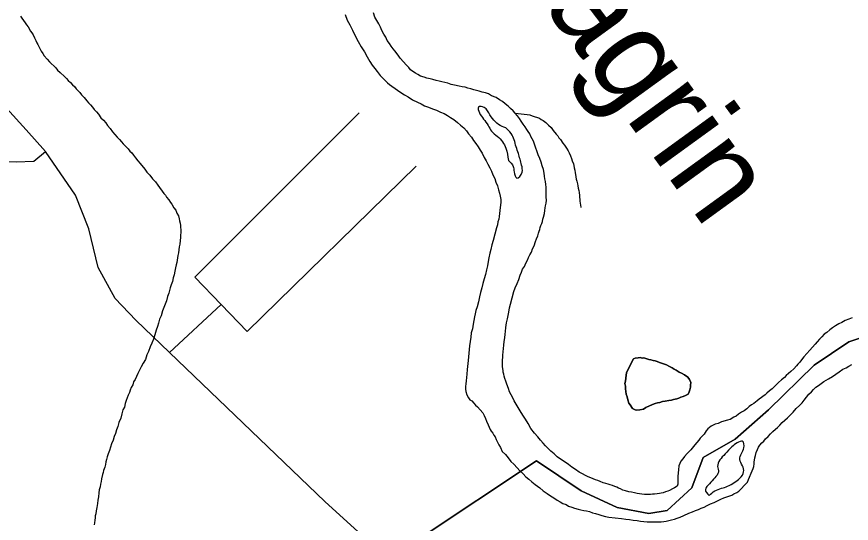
# Model space of a CAD drawing. Extents: x 0 to 34, y 0 to 22.
# Drawn here: x 4.982 to 5.822, y 15.578 to 16.088 of the extents above; entities that cross this region are included whole.
import ezdxf

# ---------------------------------------------------------------- set-up
doc = ezdxf.new("R2010")
doc.units = 0
for name, color, linetype in [('GM_X_City_Street', 7, 'Continuous'), ('GM_X_Corporation', 7, 'Continuous'), ('GM_X_County_Road', 7, 'Continuous'), ('GM_X_Major_River', 7, 'Continuous'), ('GM_X_Major_River_Text', 7, 'Continuous'), ('GM_X_Minor_Lake', 7, 'Continuous'), ('GM_X_Minor_River', 7, 'Continuous')]:
    doc.layers.add(name, color=color, linetype=linetype)

msp = doc.modelspace()

# ---------------------------------------------------------------- linework, layer by layer
at = {"layer": 'GM_X_City_Street'}
msp.add_line((5.13601, 15.74945), (5.1878, 15.79771), dxfattribs=at)
for points in [[(5.1878, 15.79771), (5.16154, 15.82528), (5.32668, 15.99079)], [(3.66207, 15.95316), (3.66945, 15.95309), (3.70802, 15.95138), (3.82256, 15.94662), (3.93928, 15.94584), (3.95443, 15.94583), (3.95914, 15.94579), (3.99989, 15.94543), (4.00319, 15.94546), (4.06636, 15.94982), (4.09371, 15.94871), (4.14798, 15.94309), (4.21615, 15.94459), (4.32069, 15.9434), (4.37523, 15.94224), (4.43166, 15.94259), (4.47924, 15.94418), (4.48737, 15.94445), (4.55589, 15.94253), (4.74017, 15.94206), (4.98153, 15.94149), (4.99934, 15.94206), (5.01105, 15.95188)], [(5.1878, 15.79771), (5.21425, 15.7707), (5.38423, 15.93717)]]:
    msp.add_lwpolyline(points, dxfattribs=at)
at = {"layer": 'GM_X_Corporation'}
for points in [[(5.89854, 16.29354), (5.8973, 15.80142), (5.87587, 15.79084), (5.84552, 15.76912), (5.81951, 15.76039), (5.78464, 15.7367), (5.73873, 15.69197), (5.70509, 15.66223), (5.67317, 15.64391), (5.66151, 15.61336), (5.63685, 15.59059), (5.61834, 15.58765), (5.58642, 15.59364), (5.55018, 15.61018), (5.50536, 15.64041), (5.38614, 15.56141), (5.45057, 15.53342), (5.44414, 15.50982), (5.51454, 15.4828), (5.51493, 15.21351), (4.90537, 15.21691)], [(4.90537, 15.21691), (5.51493, 15.21351), (5.51454, 15.4828), (5.44414, 15.50982), (5.45057, 15.53342), (5.38614, 15.56141), (5.50536, 15.64041), (5.55018, 15.61018), (5.58642, 15.59364), (5.61834, 15.58765), (5.63685, 15.59059), (5.66151, 15.61336), (5.67317, 15.64391), (5.70509, 15.66223), (5.73873, 15.69197), (5.78464, 15.7367), (5.81951, 15.76039), (5.84552, 15.76912), (5.87587, 15.79084), (5.8973, 15.80142), (5.89854, 16.29354)]]:
    msp.add_lwpolyline(points, dxfattribs=at)
at = {"layer": 'GM_X_County_Road'}
msp.add_lwpolyline([(5.44435, 15.50926), (5.36226, 15.54077), (5.34427, 15.55213), (5.29222, 15.59945), (5.13601, 15.74945), (5.10198, 15.78212), (5.08116, 15.80388), (5.06412, 15.83512), (5.05466, 15.87392), (5.04141, 15.90799), (5.01105, 15.95188), (4.99187, 15.97367), (4.81028, 16.17365), (4.78385, 16.20009), (4.7637, 16.23877)], dxfattribs=at)
at = {"layer": 'GM_X_Major_River'}
for points in [[(5.31269, 16.08985), (5.31465, 16.08416), (5.31736, 16.07924), (5.32008, 16.07394), (5.3228, 16.06827), (5.3259, 16.06259), (5.329, 16.0573), (5.3321, 16.052), (5.33481, 16.04708), (5.33752, 16.04254), (5.33984, 16.03876), (5.34253, 16.03537), (5.34484, 16.03234), (5.34792, 16.02819), (5.35061, 16.02555), (5.35291, 16.0233), (5.35522, 16.02103), (5.35752, 16.01916), (5.36555, 16.01353), (5.36861, 16.01128), (5.37243, 16.00903), (5.37625, 16.00679), (5.38046, 16.00378), (5.38542, 16.00155), (5.38924, 15.99969), (5.39268, 15.99782), (5.39649, 15.99634), (5.40068, 15.99486), (5.40449, 15.99337), (5.40869, 15.99151), (5.4125, 15.99003), (5.41556, 15.98816), (5.41862, 15.9859), (5.42206, 15.98404), (5.42589, 15.98103), (5.42895, 15.9784), (5.43202, 15.97577), (5.43471, 15.97275), (5.43702, 15.96973), (5.43972, 15.96633), (5.44203, 15.96293), (5.44434, 15.95991), (5.44666, 15.95651), (5.4486, 15.95311), (5.45053, 15.95008), (5.45247, 15.94592), (5.45479, 15.94252), (5.45635, 15.93911), (5.45828, 15.93532), (5.45984, 15.93191), (5.4614, 15.92851), (5.46334, 15.92472), (5.46452, 15.92093), (5.46608, 15.91714), (5.46688, 15.91335), (5.46806, 15.90993)], [(5.50133, 15.85397), (5.50282, 15.85702), (5.50429, 15.86122), (5.5054, 15.8639), (5.5065, 15.86695), (5.50723, 15.86962), (5.50797, 15.87153), (5.50871, 15.87344), (5.50906, 15.87534), (5.5098, 15.87725), (5.51053, 15.87954), (5.51127, 15.88145), (5.51163, 15.88374), (5.51236, 15.88565), (5.51346, 15.88946), (5.5138, 15.89251), (5.51415, 15.89517), (5.51451, 15.89708), (5.51486, 15.89975), (5.51521, 15.90279), (5.51517, 15.90583), (5.51514, 15.90888), (5.51509, 15.91306), (5.51506, 15.9161), (5.51465, 15.91876), (5.51423, 15.9218), (5.51382, 15.92446), (5.51341, 15.92712), (5.513, 15.93016), (5.5122, 15.93357), (5.51102, 15.93736), (5.50984, 15.94116), (5.50866, 15.94495), (5.5071, 15.94836), (5.50318, 15.95935), (5.50239, 15.96238), (5.50084, 15.96465), (5.49968, 15.96692), (5.49851, 15.96957), (5.49697, 15.97184), (5.49542, 15.97411), (5.49388, 15.97675), (5.49195, 15.9794), (5.49002, 15.98242), (5.48809, 15.98507), (5.48616, 15.98771), (5.48385, 15.99035), (5.48193, 15.99261), (5.47924, 15.99525), (5.47694, 15.99751), (5.47388, 15.99976), (5.4712, 16.00202), (5.46814, 16.00389), (5.4647, 16.00614), (5.46012, 16.00799), (5.45706, 16.00987), (5.45402, 16.01098), (5.45059, 16.0117), (5.44755, 16.01243), (5.44488, 16.01317), (5.44222, 16.0139), (5.43917, 16.01501), (5.43612, 16.01574), (5.43346, 16.01648), (5.43042, 16.01683), (5.42737, 16.01756), (5.42281, 16.01866), (5.41938, 16.01938), (5.41595, 16.02049), (5.41291, 16.02122), (5.40986, 16.02195), (5.4072, 16.02269), (5.40415, 16.02342), (5.40111, 16.02415), (5.39844, 16.02488), (5.39502, 16.02561), (5.39235, 16.02673), (5.38854, 16.02783), (5.38587, 16.02932), (5.38357, 16.03082), (5.3809, 16.03232), (5.3786, 16.0342), (5.37668, 16.03646), (5.37437, 16.03872), (5.36822, 16.04589), (5.36668, 16.04777), (5.36514, 16.05004), (5.36283, 16.05306), (5.3609, 16.05533), (5.35898, 16.05797), (5.35743, 16.06062), (5.35512, 16.06364), (5.35356, 16.06705), (5.35163, 16.07007), (5.34969, 16.07347), (5.34814, 16.07688), (5.34658, 16.08029), (5.34464, 16.0837), (5.34271, 16.0871), (5.34114, 16.09127)], [(5.46806, 15.90993), (5.46885, 15.9069), (5.46927, 15.90348), (5.4693, 15.90082), (5.46896, 15.89777), (5.4686, 15.89548), (5.46826, 15.89244), (5.46791, 15.88939), (5.46757, 15.88635), (5.46722, 15.88368), (5.46649, 15.88101), (5.46614, 15.87797), (5.46504, 15.87491), (5.46176, 15.86233), (5.4603, 15.85775), (5.45921, 15.85317), (5.45849, 15.84936), (5.45741, 15.84479), (5.45669, 15.84098), (5.45598, 15.83678), (5.45489, 15.83259), (5.4538, 15.82801), (5.45271, 15.82382), (5.45125, 15.81886), (5.45016, 15.81467), (5.44907, 15.81009), (5.44798, 15.80552), (5.4469, 15.80056), (5.44544, 15.7956), (5.44434, 15.79179), (5.44362, 15.78836), (5.44289, 15.7853), (5.44217, 15.78187), (5.44146, 15.77806), (5.44075, 15.77349), (5.43966, 15.7693), (5.43933, 15.76511), (5.43862, 15.76054), (5.43791, 15.75635), (5.43757, 15.75254), (5.43723, 15.74873), (5.43689, 15.74531), (5.43656, 15.7415), (5.43621, 15.73845), (5.43586, 15.73541), (5.43552, 15.73236), (5.43519, 15.7278), (5.43485, 15.72437), (5.43451, 15.72094), (5.43417, 15.7179), (5.43381, 15.71523), (5.43385, 15.71257), (5.43425, 15.71029), (5.43505, 15.70687), (5.43698, 15.70385), (5.43814, 15.70196), (5.44005, 15.70084), (5.44235, 15.69858), (5.44389, 15.69669), (5.44581, 15.69481), (5.45119, 15.68878), (5.45274, 15.68613), (5.45392, 15.6831), (5.45508, 15.68045), (5.45664, 15.67666), (5.45781, 15.67439), (5.45859, 15.67211), (5.45975, 15.67022), (5.46129, 15.66834), (5.46245, 15.66645), (5.46361, 15.66455), (5.46478, 15.66191), (5.46595, 15.65925), (5.4675, 15.65661), (5.46905, 15.65396), (5.47061, 15.64979), (5.47406, 15.64678), (5.47676, 15.64339), (5.47945, 15.63999), (5.48252, 15.63698), (5.48598, 15.63359), (5.48867, 15.63057), (5.49174, 15.62756), (5.49443, 15.62454), (5.49749, 15.62191), (5.50056, 15.61928), (5.50401, 15.61665), (5.5086, 15.61327), (5.51205, 15.61026), (5.51588, 15.60764), (5.51932, 15.60539), (5.52276, 15.60314), (5.5262, 15.60089), (5.52925, 15.5994), (5.53193, 15.59753), (5.53498, 15.59641), (5.53765, 15.59492), (5.5407, 15.59381), (5.54337, 15.5927), (5.54717, 15.59197), (5.54984, 15.59124)], [(5.63277, 15.60841), (5.63088, 15.60801), (5.62899, 15.60761), (5.62671, 15.60721), (5.62406, 15.6068), (5.62216, 15.60679), (5.61988, 15.60676), (5.61799, 15.60674), (5.61609, 15.60673), (5.61381, 15.6067), (5.61115, 15.60706), (5.60887, 15.60741), (5.60659, 15.60777), (5.60393, 15.60813), (5.60088, 15.60886), (5.59822, 15.60921), (5.59479, 15.61032), (5.59213, 15.61105), (5.58984, 15.61217), (5.58793, 15.61291), (5.58602, 15.61404), (5.58412, 15.61478), (5.58183, 15.61552), (5.57954, 15.61625), (5.57726, 15.61699), (5.57497, 15.61773), (5.57231, 15.61846), (5.56926, 15.61957), (5.56697, 15.62069), (5.56468, 15.62143), (5.56239, 15.62255), (5.56011, 15.62329), (5.55744, 15.6244), (5.55476, 15.6259), (5.55171, 15.62739), (5.54827, 15.62926), (5.54445, 15.63188), (5.54101, 15.63413), (5.53756, 15.63676), (5.52609, 15.64463), (5.52302, 15.64765), (5.51957, 15.65027), (5.51688, 15.65291), (5.5142, 15.65555), (5.51189, 15.65819), (5.5092, 15.6612), (5.5065, 15.6646), (5.50342, 15.66837), (5.49958, 15.6729), (5.49686, 15.6782), (5.49416, 15.68235), (5.49145, 15.68651), (5.48875, 15.69067), (5.48681, 15.69407), (5.48488, 15.69748), (5.48294, 15.70088), (5.48139, 15.70391), (5.47984, 15.70694), (5.47828, 15.70996), (5.47711, 15.71337), (5.47554, 15.71754), (5.47437, 15.72057), (5.47358, 15.72323), (5.47279, 15.72588), (5.47239, 15.72778), (5.47161, 15.72967), (5.47159, 15.73158), (5.47117, 15.735), (5.47115, 15.7369), (5.47112, 15.73956), (5.47109, 15.74222), (5.47144, 15.74451), (5.47142, 15.74679), (5.47176, 15.75022), (5.4721, 15.75364), (5.47244, 15.75707), (5.47278, 15.7605), (5.4735, 15.76431), (5.47383, 15.76811), (5.47418, 15.77078), (5.47452, 15.77459), (5.47522, 15.77954), (5.47594, 15.78335), (5.47666, 15.78678), (5.47738, 15.79021), (5.47809, 15.7944), (5.47919, 15.79822), (5.48246, 15.8108), (5.48394, 15.81462), (5.48579, 15.81882), (5.48764, 15.82302), (5.48873, 15.82722), (5.49021, 15.83027), (5.49132, 15.83333), (5.49318, 15.83601), (5.49466, 15.83945), (5.49615, 15.84251), (5.49726, 15.84518), (5.49874, 15.84786), (5.50023, 15.85053), (5.50133, 15.85397)], [(5.82285, 15.78449), (5.81945, 15.78294), (5.81605, 15.78176), (5.81265, 15.77983), (5.80963, 15.77828), (5.80624, 15.77634), (5.80322, 15.77441), (5.80059, 15.77248), (5.79758, 15.76979), (5.79495, 15.76786), (5.79232, 15.76517), (5.79007, 15.76287), (5.78782, 15.76019), (5.78557, 15.75788), (5.78295, 15.75481), (5.78033, 15.75174), (5.77732, 15.74867), (5.77433, 15.74522), (5.77208, 15.74215), (5.77021, 15.73985), (5.76833, 15.73793), (5.76684, 15.73602), (5.76421, 15.73295), (5.76121, 15.73025), (5.75895, 15.72833), (5.7567, 15.72641), (5.75482, 15.72449), (5.75181, 15.72217), (5.7488, 15.71948), (5.74505, 15.71564), (5.74242, 15.71295), (5.73979, 15.71102), (5.73716, 15.70872), (5.73528, 15.7068), (5.72926, 15.70255), (5.72738, 15.70101), (5.72399, 15.69832), (5.72173, 15.69677), (5.71947, 15.69523), (5.71684, 15.69292), (5.71421, 15.69099), (5.71157, 15.68945), (5.70855, 15.68751), (5.7063, 15.68559), (5.70403, 15.68443), (5.70026, 15.68211), (5.69761, 15.68132), (5.69156, 15.67974), (5.68816, 15.67818), (5.68513, 15.67739), (5.68098, 15.67545), (5.67759, 15.67275), (5.6761, 15.67084), (5.67386, 15.66739), (5.67198, 15.66547), (5.67011, 15.66317), (5.66861, 15.66125), (5.66674, 15.65895), (5.66449, 15.65665), (5.66075, 15.65167), (5.65888, 15.64975), (5.657, 15.64783), (5.65438, 15.64476), (5.6525, 15.64246), (5.65063, 15.64016), (5.64841, 15.63557), (5.64807, 15.63138), (5.64739, 15.62491), (5.64742, 15.62187), (5.64748, 15.61693), (5.64674, 15.61502), (5.6441, 15.61347), (5.64222, 15.61231), (5.6392, 15.61076), (5.63731, 15.60998), (5.63504, 15.6092), (5.63277, 15.60841)], [(5.54984, 15.59124), (5.55288, 15.59051), (5.55555, 15.59015), (5.55859, 15.58942), (5.56164, 15.58831), (5.56468, 15.58758), (5.56811, 15.58647), (5.57116, 15.58536), (5.57459, 15.58464), (5.57801, 15.58391), (5.59093, 15.58252), (5.59511, 15.5818), (5.59892, 15.58145), (5.60272, 15.58073), (5.60652, 15.58039), (5.60994, 15.57966), (5.61336, 15.57931), (5.61678, 15.57897), (5.61944, 15.57899), (5.6221, 15.57902), (5.62589, 15.57906), (5.62855, 15.57908), (5.63082, 15.57911), (5.63348, 15.57951), (5.63575, 15.57991), (5.6384, 15.58032), (5.64105, 15.58111), (5.64408, 15.5819), (5.64673, 15.58269), (5.64975, 15.58386), (5.65353, 15.58541), (5.65843, 15.58775), (5.66221, 15.58931), (5.66524, 15.59048), (5.66826, 15.59165), (5.6709, 15.59281), (5.67393, 15.59398), (5.67695, 15.59554), (5.68035, 15.59709), (5.68412, 15.59865), (5.68752, 15.6002), (5.69092, 15.60176), (5.69394, 15.60331), (5.69772, 15.60449), (5.69999, 15.60527), (5.70188, 15.60605), (5.70376, 15.60721), (5.70678, 15.60876), (5.70905, 15.60993), (5.7113, 15.61223), (5.71467, 15.61607), (5.71767, 15.61914), (5.71878, 15.62181), (5.72248, 15.6306), (5.72321, 15.63289), (5.72395, 15.6348), (5.7243, 15.63746), (5.72428, 15.63936), (5.72463, 15.64127), (5.72499, 15.64355), (5.72572, 15.64584), (5.72645, 15.6489), (5.72755, 15.65195), (5.72867, 15.65424), (5.73016, 15.65616), (5.73203, 15.65846), (5.73391, 15.66038), (5.73578, 15.66268), (5.73841, 15.66499), (5.74066, 15.66767), (5.74329, 15.66998), (5.74592, 15.67229), (5.7478, 15.67421), (5.75005, 15.67651), (5.75268, 15.6792), (5.75531, 15.68151), (5.75794, 15.68382), (5.76056, 15.68651), (5.76356, 15.68958), (5.76656, 15.69303), (5.76995, 15.69611), (5.77257, 15.6988), (5.77482, 15.70148), (5.77706, 15.70455), (5.7793, 15.70761), (5.78194, 15.70992), (5.78419, 15.71223), (5.78644, 15.71453), (5.78907, 15.71646), (5.79171, 15.71838), (5.79434, 15.72031), (5.79925, 15.72302), (5.80302, 15.72534), (5.80641, 15.72766), (5.8098, 15.72997), (5.81356, 15.73267), (5.81696, 15.73423), (5.8196, 15.73577), (5.82262, 15.73733)]]:
    msp.add_lwpolyline(points, dxfattribs=at)
for points in [[(5.45609, 15.99262), (5.45264, 15.99628), (5.44696, 15.99661), (5.44776, 15.99092), (5.45198, 15.9845), (5.45658, 15.97808), (5.46004, 15.97242), (5.46577, 15.96715), (5.47112, 15.9615), (5.47458, 15.95508), (5.47696, 15.94295)], [(5.47433, 15.97567), (5.46719, 15.97893), (5.46107, 15.98496), (5.45609, 15.99262)], [(5.47696, 15.94295), (5.48194, 15.93691), (5.48274, 15.93122), (5.48544, 15.92517), (5.4907, 15.93091), (5.49026, 15.93812), (5.4887, 15.94418), (5.48713, 15.94987), (5.48481, 15.95668), (5.48285, 15.9635), (5.47977, 15.96993), (5.47433, 15.97567)], [(5.67909, 15.60558), (5.68473, 15.61019), (5.69153, 15.6129), (5.69758, 15.61485), (5.70437, 15.6187), (5.71002, 15.62293), (5.71376, 15.62941), (5.71257, 15.63548), (5.70987, 15.64191), (5.71171, 15.648), (5.71394, 15.65372), (5.71275, 15.66016), (5.70708, 15.65859), (5.70194, 15.6547)], [(5.70194, 15.6547), (5.69504, 15.64748), (5.68978, 15.64136), (5.68756, 15.63489), (5.68837, 15.6292), (5.68462, 15.62347), (5.67937, 15.61735), (5.67524, 15.61162), (5.67909, 15.60558)]]:
    msp.add_spline(points, degree=3, dxfattribs=at)
at = {"layer": 'GM_X_Minor_Lake'}
for points in [[(5.60257, 15.74296), (5.60278, 15.74314), (5.60467, 15.74392), (5.60771, 15.74433), (5.6096, 15.74435), (5.61151, 15.74399), (5.6134, 15.74401), (5.61645, 15.74328), (5.61835, 15.74253), (5.62026, 15.74217), (5.62254, 15.74144), (5.62482, 15.74108), (5.62673, 15.74034), (5.62902, 15.7396), (5.63626, 15.73701), (5.63855, 15.73589), (5.64198, 15.73402), (5.64389, 15.7329), (5.64581, 15.73178), (5.64886, 15.7299), (5.65115, 15.72878), (5.65421, 15.72691), (5.65765, 15.72467), (5.65919, 15.7224), (5.66075, 15.71937), (5.6604, 15.7167), (5.66042, 15.7148), (5.65969, 15.71213), (5.65896, 15.70984), (5.65785, 15.70755), (5.6552, 15.70638), (5.65294, 15.70522), (5.65067, 15.70444), (5.6484, 15.70366), (5.64651, 15.70287), (5.6431, 15.70208), (5.64121, 15.70168), (5.63856, 15.70127), (5.63477, 15.70048), (5.63212, 15.70007), (5.62947, 15.69928), (5.6272, 15.69888), (5.62455, 15.69809), (5.6219, 15.69731), (5.61548, 15.6942), (5.61284, 15.69265), (5.60944, 15.69186), (5.60641, 15.69145), (5.6045, 15.69181), (5.60183, 15.69331), (5.59951, 15.6967), (5.59835, 15.6986), (5.59718, 15.70201), (5.59638, 15.70504), (5.59559, 15.7077), (5.59518, 15.71036), (5.59478, 15.71302), (5.59474, 15.71568), (5.59433, 15.71834), (5.59469, 15.72062), (5.59503, 15.72367), (5.59538, 15.72671), (5.59573, 15.729), (5.60257, 15.74296)], [(5.60257, 15.74296), (5.59573, 15.729), (5.59538, 15.72671), (5.59503, 15.72367), (5.59469, 15.72062), (5.59433, 15.71834), (5.59474, 15.71568), (5.59478, 15.71302), (5.59518, 15.71036), (5.59559, 15.7077), (5.59638, 15.70504), (5.59718, 15.70201), (5.59835, 15.6986), (5.59951, 15.6967), (5.60183, 15.69331), (5.6045, 15.69181), (5.60641, 15.69145), (5.60944, 15.69186), (5.61284, 15.69265), (5.61548, 15.6942), (5.6219, 15.69731), (5.62455, 15.69809), (5.6272, 15.69888), (5.62947, 15.69928), (5.63212, 15.70007), (5.63477, 15.70048), (5.63856, 15.70127), (5.64121, 15.70168), (5.6431, 15.70208), (5.64651, 15.70287), (5.6484, 15.70366), (5.65067, 15.70444), (5.65294, 15.70522)], [(5.65294, 15.70522), (5.6552, 15.70638), (5.65785, 15.70755), (5.65896, 15.70984), (5.65969, 15.71213), (5.66042, 15.7148), (5.6604, 15.7167), (5.66075, 15.71937), (5.65919, 15.7224), (5.65765, 15.72467), (5.65421, 15.72691), (5.65115, 15.72878), (5.64886, 15.7299), (5.64581, 15.73178), (5.64389, 15.7329), (5.64198, 15.73402), (5.63855, 15.73589), (5.63626, 15.73701), (5.62902, 15.7396), (5.62673, 15.74034), (5.62482, 15.74108), (5.62254, 15.74144), (5.62026, 15.74217), (5.61835, 15.74253), (5.61645, 15.74328), (5.6134, 15.74401), (5.61151, 15.74399), (5.6096, 15.74435), (5.60771, 15.74433), (5.60467, 15.74392), (5.60278, 15.74314), (5.60257, 15.74296)]]:
    msp.add_lwpolyline(points, dxfattribs=at)
at = {"layer": 'GM_X_Minor_River'}
for points in [[(4.98591, 16.08816), (4.98745, 16.08589), (4.989, 16.08362), (4.99054, 16.08136), (4.99208, 16.07947), (4.99362, 16.0772), (4.99595, 16.07304), (4.99749, 16.07116), (4.99865, 16.06927), (5.0002, 16.06623), (5.00137, 16.06359), (5.00253, 16.06131), (5.00331, 16.05942), (5.00447, 16.05753), (5.0068, 16.05299), (5.00835, 16.05034), (5.00989, 16.04807), (5.01297, 16.04468), (5.01528, 16.04204), (5.02142, 16.03601), (5.02334, 16.03375), (5.02602, 16.03149), (5.03024, 16.02735), (5.03216, 16.02547), (5.03409, 16.0232), (5.03638, 16.02133), (5.03831, 16.01906), (5.04023, 16.01718), (5.04215, 16.01492), (5.04407, 16.01303), (5.04561, 16.01114), (5.04753, 16.00888), (5.05022, 16.00624), (5.05291, 16.00285), (5.05445, 16.00096), (5.05638, 15.9987), (5.0583, 15.99643)], [(5.0583, 15.99643), (5.06022, 15.99417), (5.06253, 15.99191), (5.06445, 15.98927), (5.06677, 15.98587), (5.06946, 15.98323), (5.07176, 15.98059), (5.07369, 15.97795), (5.07638, 15.97493), (5.0787, 15.97153), (5.081, 15.96889), (5.08331, 15.96625), (5.08561, 15.96399), (5.08754, 15.96173), (5.08946, 15.95946), (5.09176, 15.9572), (5.09445, 15.95457), (5.09599, 15.9523), (5.09791, 15.95042), (5.09984, 15.94815), (5.10176, 15.94551), (5.10407, 15.94249), (5.10638, 15.93985), (5.111, 15.93419), (5.11331, 15.93117), (5.116, 15.92815), (5.1187, 15.92437), (5.12177, 15.92136), (5.12409, 15.91796), (5.13025, 15.90965), (5.13179, 15.90777), (5.13295, 15.90588), (5.13526, 15.90324), (5.13681, 15.90059), (5.13835, 15.8987), (5.14028, 15.8953), (5.14221, 15.89265), (5.14338, 15.88962), (5.14493, 15.88698), (5.14573, 15.88394), (5.14613, 15.88204), (5.14653, 15.87976), (5.14694, 15.87748), (5.14696, 15.87559), (5.14737, 15.87293), (5.1474, 15.86988), (5.14705, 15.86798), (5.14707, 15.86531), (5.14673, 15.86227), (5.14639, 15.85846), (5.14566, 15.85579), (5.14532, 15.85275), (5.14497, 15.8497), (5.14424, 15.84703), (5.14389, 15.84474), (5.14354, 15.84246), (5.14318, 15.84017), (5.14283, 15.83789), (5.1421, 15.83484), (5.14138, 15.83141), (5.14067, 15.82759), (5.13956, 15.82454), (5.13884, 15.82111), (5.13774, 15.81768), (5.13664, 15.81462), (5.13591, 15.81195), (5.13518, 15.80928), (5.13408, 15.80585), (5.13299, 15.80165), (5.12893, 15.79134), (5.12747, 15.78638), (5.12599, 15.78295), (5.12489, 15.77913), (5.12379, 15.7757), (5.1227, 15.77188), (5.12123, 15.7673), (5.11976, 15.76311), (5.11829, 15.75891), (5.11643, 15.75509), (5.11497, 15.75051), (5.11311, 15.74707), (5.11164, 15.74249), (5.10941, 15.73866), (5.10755, 15.73522), (5.10569, 15.73178), (5.10421, 15.72834), (5.10273, 15.72528), (5.10124, 15.72223), (5.09975, 15.71993), (5.09903, 15.71688), (5.09754, 15.7142), (5.09643, 15.71153), (5.0957, 15.70924), (5.09421, 15.70656), (5.09348, 15.70389), (5.09237, 15.70122), (5.09127, 15.69816), (5.09055, 15.69435), (5.08906, 15.69168), (5.08797, 15.68786), (5.08688, 15.68329)], [(5.48366, 15.99058), (5.49602, 15.98895), (5.49868, 15.98859), (5.50096, 15.98786), (5.50821, 15.98526), (5.51011, 15.98414), (5.51203, 15.98302), (5.5147, 15.98114), (5.51739, 15.97851), (5.52008, 15.97587), (5.52201, 15.97285), (5.52508, 15.96945), (5.52662, 15.96757), (5.52778, 15.96568), (5.52932, 15.96379), (5.53164, 15.96039), (5.53356, 15.95813), (5.53549, 15.9551), (5.53704, 15.95245), (5.5382, 15.95056), (5.53937, 15.94753), (5.54054, 15.94488), (5.54133, 15.94261), (5.5425, 15.93958), (5.5429, 15.93768), (5.54331, 15.9354), (5.54371, 15.93312), (5.54412, 15.93046), (5.54452, 15.92857), (5.54493, 15.92629), (5.54533, 15.92401), (5.54573, 15.92211), (5.54652, 15.91946), (5.54693, 15.91718), (5.54733, 15.9149), (5.54774, 15.91262), (5.54814, 15.91072), (5.54855, 15.90768), (5.549, 15.90198), (5.54942, 15.8978), (5.54982, 15.89591), (5.54983, 15.89553)], [(5.08688, 15.68329), (5.08503, 15.67909), (5.08394, 15.67489), (5.08245, 15.67183), (5.08174, 15.66802), (5.08025, 15.66496), (5.07916, 15.66115), (5.07768, 15.65771), (5.07658, 15.65428), (5.07548, 15.65084), (5.07438, 15.64741), (5.07328, 15.64436), (5.07255, 15.64169), (5.07181, 15.6394), (5.07146, 15.63673), (5.07073, 15.63406), (5.06963, 15.63063), (5.06928, 15.62872), (5.06854, 15.62681), (5.06745, 15.62224), (5.0671, 15.61957), (5.06637, 15.6169), (5.06602, 15.61424), (5.0653, 15.61119), (5.06495, 15.60814), (5.06462, 15.60433), (5.06389, 15.6009), (5.06355, 15.59748), (5.06284, 15.59367), (5.06212, 15.59023), (5.06177, 15.58719), (5.06104, 15.58528), (5.06106, 15.583), (5.06071, 15.58071), (5.06036, 15.57805), (5.06, 15.57614)]]:
    msp.add_lwpolyline(points, dxfattribs=at)

# ---------------------------------------------------------------- texts
at = {"layer": 'GM_X_Major_River_Text'}
msp.add_text('Chagrin', height=0.094765, rotation=305.95019, dxfattribs=at).set_placement((5.41571, 16.23185))

doc.saveas('drawing.dxf')
